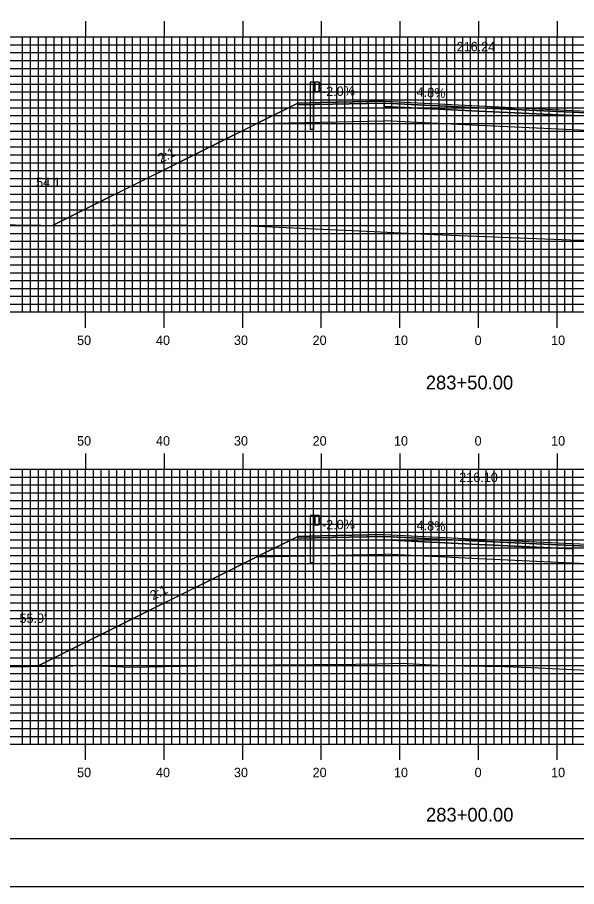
# Model space of a CAD drawing. Extents: x 1811767 to 1812110, y 442591 to 442811.
# Drawn here: x 1811874.3 to 1811945.4, y 442590.5 to 442701.2 of the extents above; entities that cross this region are included whole.
import ezdxf

# ---------------------------------------------------------------- set-up
doc = ezdxf.new("R2010")
doc.units = 0
for name, color, linetype in [('ANNOTATION', 7, 'Continuous'), ('BORDER', 7, 'Continuous'), ('D_Guardrail_Beam_Lt', 7, 'Continuous'), ('D_Roadway_Centerline', 7, 'Continuous'), ('D_Roadway_Centerline_Text', 7, 'Continuous'), ('D_Roadway_Edge_Shoulder', 7, 'Continuous'), ('D_Roadway_Edge_TW', 7, 'Continuous'), ('D_Roadway_Pavement', 7, 'Continuous'), ('D_Roadway_SlopeLines', 7, 'Continuous'), ('D_Roadway_SubGrade', 7, 'Continuous'), ('D_Text_Standard', 7, 'Continuous'), ('H_V ANNOTATION', 7, 'Continuous'), ('MAJOR', 7, 'Continuous'), ('MINOR', 7, 'Continuous'), ('PLOT BOUNDARY', 7, 'Continuous'), ('S_Roadway_Centerline', 7, 'Continuous')]:
    doc.layers.add(name, color=color, linetype=linetype)

msp = doc.modelspace()

# ---------------------------------------------------------------- linework, layer by layer
at = {"layer": 'BORDER'}
msp.add_lwpolyline([(1811783.32, 442596.67), (1812103.32, 442596.67), (1812103.32, 442806.67), (1811783.32, 442806.67)], close=True, dxfattribs=at)
at = {"layer": 'D_Guardrail_Beam_Lt'}
for p, q in [((1811911.49, 442692.91), (1811911.49, 442686.91)), ((1811911.96, 442692.91), (1811911.49, 442692.91)), ((1811912.65, 442692.91), (1811911.96, 442692.91)), ((1811911.96, 442692.91), (1811911.96, 442691.74)), ((1811912.02, 442692.91), (1811912.02, 442691.74)), ((1811912.12, 442692.91), (1811912.12, 442691.74)), ((1811912.65, 442691.74), (1811912.65, 442692.91)), ((1811912.65, 442692.82), (1811912.72, 442692.81)), ((1811912.74, 442692.8), (1811912.88, 442692.7)), ((1811911.96, 442691.74), (1811912.65, 442691.74)), ((1811911.98, 442686.91), (1811911.98, 442691.74)), ((1811912.65, 442692.36), (1811912.65, 442692.29)), ((1811912.72, 442691.84), (1811912.65, 442691.82)), ((1811912.88, 442692.56), (1811912.68, 442692.42)), ((1811912.68, 442692.22), (1811912.88, 442692.09)), ((1811912.88, 442691.94), (1811912.74, 442691.84)), ((1811911.98, 442686.91), (1811911.49, 442686.91)), ((1811911.49, 442637.77), (1811911.49, 442631.77)), ((1811911.96, 442637.77), (1811911.49, 442637.77)), ((1811912.65, 442637.77), (1811911.96, 442637.77)), ((1811911.96, 442637.77), (1811911.96, 442636.6)), ((1811912.02, 442637.77), (1811912.02, 442636.6)), ((1811912.12, 442637.77), (1811912.12, 442636.6)), ((1811912.65, 442636.6), (1811912.65, 442637.77)), ((1811912.65, 442637.68), (1811912.72, 442637.67)), ((1811912.88, 442637.42), (1811912.68, 442637.28)), ((1811912.74, 442637.66), (1811912.88, 442637.56)), ((1811911.96, 442636.6), (1811912.65, 442636.6)), ((1811911.98, 442631.77), (1811911.98, 442636.6)), ((1811912.65, 442637.22), (1811912.65, 442637.15)), ((1811912.72, 442636.7), (1811912.65, 442636.68)), ((1811912.68, 442637.08), (1811912.88, 442636.95)), ((1811912.88, 442636.8), (1811912.74, 442636.7)), ((1811911.98, 442631.77), (1811911.49, 442631.77))]:
    msp.add_line(p, q, dxfattribs=at)
for centre, major_axis, start_param, end_param in [((1811912.71, 442692.77), (0.0417, 0), 0.959931, 1.376053), ((1811912.83, 442692.63), (0.0877, 0), 5.323254, 7.243116), ((1811912.73, 442692.36), (-0.0789, 0), 5.323254, 6.283185), ((1811912.73, 442692.29), (-0.0789, 0), 6.283185, 7.243116), ((1811912.71, 442691.88), (0.0417, 0), 4.907132, 5.323254), ((1811912.83, 442692.01), (0.0877, 0), 5.323254, 7.243116), ((1811912.71, 442637.63), (0.0417, 0), 0.959931, 1.376053), ((1811912.83, 442637.49), (0.0877, 0), 5.323254, 7.243116), ((1811912.73, 442637.22), (-0.0789, 0), 5.323254, 6.283185), ((1811912.73, 442637.15), (-0.0789, 0), 6.283185, 7.243116), ((1811912.71, 442636.74), (0.0417, 0), 4.907132, 5.323254), ((1811912.83, 442636.88), (0.0877, 0), 5.323254, 7.243116)]:
    msp.add_ellipse(centre, major_axis=major_axis, ratio=0.995501, start_param=start_param, end_param=end_param, dxfattribs=at)
at = {"layer": 'D_Roadway_Centerline'}
for points in [[(1811878.79, 442674.7), (1811904.71, 442687.66), (1811909.92, 442690.26), (1811912.92, 442690.32), (1811920.92, 442690.48), (1811932.92, 442689.91), (1811944.92, 442689.33), (1811952.92, 442688.95), (1811955.92, 442688.8), (1811961.45, 442686.04), (1811989.08, 442672.22)], [(1811876.82, 442618.58), (1811904.71, 442632.52), (1811909.92, 442635.12), (1811912.92, 442635.18), (1811920.92, 442635.34), (1811932.92, 442634.77), (1811944.92, 442634.19), (1811952.92, 442633.81), (1811955.92, 442633.66), (1811961.45, 442630.9), (1811989.37, 442616.93)]]:
    msp.add_lwpolyline(points, dxfattribs=at)
at = {"layer": 'D_Roadway_Edge_Shoulder'}
for points in [[(1811920.92, 442690.48), (1811912.92, 442690.32), (1811912.92, 442690.32), (1811909.92, 442690.26), (1811909.92, 442690.01), (1811920.92, 442690.23)], [(1811944.92, 442689.33), (1811952.92, 442688.95), (1811952.92, 442688.95), (1811955.92, 442688.8), (1811955.92, 442688.55), (1811944.92, 442689.08)], [(1811920.92, 442635.34), (1811912.92, 442635.18), (1811912.92, 442635.18), (1811909.92, 442635.12), (1811909.92, 442634.87), (1811920.92, 442635.09)], [(1811944.92, 442634.19), (1811952.92, 442633.81), (1811952.92, 442633.81), (1811955.92, 442633.66), (1811955.92, 442633.41), (1811944.92, 442633.94)]]:
    msp.add_lwpolyline(points, close=True, dxfattribs=at)
at = {"layer": 'D_Roadway_Edge_TW'}
for points in [[(1811920.92, 442690.23), (1811920.92, 442690.48), (1811932.92, 442689.91), (1811944.92, 442689.33), (1811944.92, 442689.08), (1811932.92, 442689.66)], [(1811920.92, 442635.09), (1811920.92, 442635.34), (1811932.92, 442634.77), (1811944.92, 442634.19), (1811944.92, 442633.94), (1811932.92, 442634.52)]]:
    msp.add_lwpolyline(points, close=True, dxfattribs=at)
at = {"layer": 'D_Roadway_Pavement'}
for points in [[(1811920.92, 442689.81), (1811920.92, 442690.23), (1811932.92, 442689.66), (1811944.92, 442689.08), (1811944.92, 442688.66), (1811932.92, 442689.24)], [(1811920.92, 442634.68), (1811920.92, 442635.09), (1811932.92, 442634.52), (1811944.92, 442633.94), (1811944.92, 442633.52), (1811932.92, 442634.1)]]:
    msp.add_lwpolyline(points, close=True, dxfattribs=at)
for points in [[(1811920.92, 442690.23), (1811920.92, 442689.81)], [(1811944.92, 442689.08), (1811944.92, 442688.66)], [(1811920.92, 442635.09), (1811920.92, 442634.68)], [(1811944.92, 442633.94), (1811944.92, 442633.52)]]:
    msp.add_lwpolyline(points, dxfattribs=at)
at = {"layer": 'D_Roadway_SlopeLines'}
for points in [[(1811909.92, 442690.26), (1811878.79, 442674.7)], [(1811909.92, 442635.12), (1811876.82, 442618.58)]]:
    msp.add_lwpolyline(points, dxfattribs=at)
at = {"layer": 'D_Roadway_SubGrade'}
for points in [[(1811920.92, 442689.81), (1811920.92, 442690.23), (1811909.92, 442690.01), (1811909.92, 442690.26), (1811904.71, 442687.66), (1811920.92, 442687.98)], [(1811920.92, 442687.98), (1811920.92, 442690.23), (1811920.92, 442689.81), (1811932.92, 442689.24), (1811944.92, 442688.66), (1811944.92, 442689.08), (1811944.92, 442686.83), (1811932.92, 442687.41)], [(1811944.92, 442688.66), (1811944.92, 442689.08), (1811955.92, 442688.55), (1811955.92, 442688.8), (1811961.45, 442686.04), (1811944.92, 442686.83)], [(1811920.92, 442634.68), (1811920.92, 442635.09), (1811909.92, 442634.87), (1811909.92, 442635.12), (1811904.71, 442632.52), (1811920.92, 442632.84)], [(1811920.92, 442632.84), (1811920.92, 442635.09), (1811920.92, 442634.68), (1811932.92, 442634.1), (1811944.92, 442633.52), (1811944.92, 442633.94), (1811944.92, 442631.69), (1811932.92, 442632.27)], [(1811944.92, 442633.52), (1811944.92, 442633.94), (1811955.92, 442633.41), (1811955.92, 442633.66), (1811961.45, 442630.9), (1811944.92, 442631.69)]]:
    msp.add_lwpolyline(points, close=True, dxfattribs=at)
at = {"layer": 'MAJOR'}
for p, q in [((1811882.92, 442700.67), (1811882.92, 442698.67)), ((1811892.92, 442700.67), (1811892.92, 442698.67)), ((1811902.92, 442700.67), (1811902.92, 442698.67)), ((1811912.92, 442700.67), (1811912.92, 442698.67)), ((1811922.92, 442700.67), (1811922.92, 442698.67)), ((1811932.92, 442700.67), (1811932.92, 442698.67)), ((1811942.92, 442700.67), (1811942.92, 442698.67)), ((1811792.92, 442698.67), (1812072.92, 442698.67)), ((1811792.92, 442698.67), (1812072.92, 442698.67)), ((1811882.92, 442663.67), (1811882.92, 442698.67)), ((1811892.92, 442663.67), (1811892.92, 442698.67)), ((1811902.92, 442663.67), (1811902.92, 442698.67)), ((1811912.92, 442663.67), (1811912.92, 442698.67)), ((1811922.92, 442663.67), (1811922.92, 442698.67)), ((1811932.92, 442663.67), (1811932.92, 442698.67)), ((1811942.92, 442663.67), (1811942.92, 442698.67)), ((1811792.92, 442693.67), (1812072.92, 442693.67)), ((1811792.92, 442688.67), (1812072.92, 442688.67)), ((1811792.92, 442683.67), (1812072.92, 442683.67)), ((1811792.92, 442678.67), (1812072.92, 442678.67)), ((1811792.92, 442673.67), (1812072.92, 442673.67)), ((1811792.92, 442668.67), (1812072.92, 442668.67)), ((1811792.92, 442663.67), (1812072.92, 442663.67)), ((1811792.92, 442663.67), (1812072.92, 442663.67)), ((1811882.92, 442661.66), (1811882.92, 442663.67)), ((1811892.92, 442661.66), (1811892.92, 442663.67)), ((1811902.92, 442661.66), (1811902.92, 442663.67)), ((1811912.92, 442661.66), (1811912.92, 442663.67)), ((1811922.92, 442661.66), (1811922.92, 442663.67)), ((1811932.92, 442661.66), (1811932.92, 442663.67)), ((1811942.92, 442661.66), (1811942.92, 442663.67)), ((1811882.92, 442645.67), (1811882.92, 442643.67)), ((1811892.92, 442645.67), (1811892.92, 442643.67)), ((1811902.92, 442645.67), (1811902.92, 442643.67)), ((1811912.92, 442645.67), (1811912.92, 442643.67)), ((1811922.92, 442645.67), (1811922.92, 442643.67)), ((1811932.92, 442645.67), (1811932.92, 442643.67)), ((1811942.92, 442645.67), (1811942.92, 442643.67)), ((1811792.92, 442643.67), (1812072.92, 442643.67)), ((1811792.92, 442643.67), (1812072.92, 442643.67)), ((1811882.92, 442608.67), (1811882.92, 442643.67)), ((1811892.92, 442608.67), (1811892.92, 442643.67)), ((1811902.92, 442608.67), (1811902.92, 442643.67)), ((1811912.92, 442608.67), (1811912.92, 442643.67)), ((1811922.92, 442608.67), (1811922.92, 442643.67)), ((1811932.92, 442608.67), (1811932.92, 442643.67)), ((1811942.92, 442608.67), (1811942.92, 442643.67)), ((1811792.92, 442638.67), (1812072.92, 442638.67)), ((1811792.92, 442633.67), (1812072.92, 442633.67)), ((1811792.92, 442628.67), (1812072.92, 442628.67)), ((1811792.92, 442623.67), (1812072.92, 442623.67)), ((1811792.92, 442618.67), (1812072.92, 442618.67)), ((1811792.92, 442613.67), (1812072.92, 442613.67)), ((1811792.92, 442608.67), (1812072.92, 442608.67)), ((1811792.92, 442608.67), (1812072.92, 442608.67)), ((1811882.92, 442606.66), (1811882.92, 442608.67)), ((1811892.92, 442606.66), (1811892.92, 442608.67)), ((1811902.92, 442606.66), (1811902.92, 442608.67)), ((1811912.92, 442606.66), (1811912.92, 442608.67)), ((1811922.92, 442606.66), (1811922.92, 442608.67)), ((1811932.92, 442606.66), (1811932.92, 442608.67)), ((1811942.92, 442606.66), (1811942.92, 442608.67))]:
    msp.add_line(p, q, dxfattribs=at)
at = {"layer": 'MINOR'}
for p, q in [((1811874.92, 442663.67), (1811874.92, 442698.67)), ((1811875.92, 442663.67), (1811875.92, 442698.67)), ((1811876.92, 442663.67), (1811876.92, 442698.67)), ((1811877.92, 442663.67), (1811877.92, 442698.67)), ((1811878.92, 442663.67), (1811878.92, 442698.67)), ((1811879.92, 442663.67), (1811879.92, 442698.67)), ((1811880.92, 442663.67), (1811880.92, 442698.67)), ((1811881.92, 442663.67), (1811881.92, 442698.67)), ((1811883.92, 442663.67), (1811883.92, 442698.67)), ((1811884.92, 442663.67), (1811884.92, 442698.67)), ((1811885.92, 442663.67), (1811885.92, 442698.67)), ((1811886.92, 442663.67), (1811886.92, 442698.67)), ((1811887.92, 442663.67), (1811887.92, 442698.67)), ((1811888.92, 442663.67), (1811888.92, 442698.67)), ((1811889.92, 442663.67), (1811889.92, 442698.67)), ((1811890.92, 442663.67), (1811890.92, 442698.67)), ((1811891.92, 442663.67), (1811891.92, 442698.67)), ((1811893.92, 442663.67), (1811893.92, 442698.67)), ((1811894.92, 442663.67), (1811894.92, 442698.67)), ((1811895.92, 442663.67), (1811895.92, 442698.67)), ((1811896.92, 442663.67), (1811896.92, 442698.67)), ((1811897.92, 442663.67), (1811897.92, 442698.67)), ((1811898.92, 442663.67), (1811898.92, 442698.67)), ((1811899.92, 442663.67), (1811899.92, 442698.67)), ((1811900.92, 442663.67), (1811900.92, 442698.67)), ((1811901.92, 442663.67), (1811901.92, 442698.67)), ((1811903.92, 442663.67), (1811903.92, 442698.67)), ((1811904.92, 442663.67), (1811904.92, 442698.67)), ((1811905.92, 442663.67), (1811905.92, 442698.67)), ((1811906.92, 442663.67), (1811906.92, 442698.67)), ((1811907.92, 442663.67), (1811907.92, 442698.67)), ((1811908.92, 442663.67), (1811908.92, 442698.67)), ((1811909.92, 442663.67), (1811909.92, 442698.67)), ((1811910.92, 442663.67), (1811910.92, 442698.67)), ((1811911.92, 442663.67), (1811911.92, 442698.67)), ((1811913.92, 442663.67), (1811913.92, 442698.67)), ((1811914.92, 442663.67), (1811914.92, 442698.67)), ((1811915.92, 442663.67), (1811915.92, 442698.67)), ((1811916.92, 442663.67), (1811916.92, 442698.67)), ((1811917.92, 442663.67), (1811917.92, 442698.67)), ((1811918.92, 442663.67), (1811918.92, 442698.67)), ((1811919.92, 442663.67), (1811919.92, 442698.67)), ((1811920.92, 442663.67), (1811920.92, 442698.67)), ((1811921.92, 442663.67), (1811921.92, 442698.67)), ((1811923.92, 442663.67), (1811923.92, 442698.67)), ((1811924.92, 442663.67), (1811924.92, 442698.67)), ((1811925.92, 442663.67), (1811925.92, 442698.67)), ((1811926.92, 442663.67), (1811926.92, 442698.67)), ((1811927.92, 442663.67), (1811927.92, 442698.67)), ((1811928.92, 442663.67), (1811928.92, 442698.67)), ((1811929.92, 442663.67), (1811929.92, 442698.67)), ((1811930.92, 442663.67), (1811930.92, 442698.67)), ((1811931.92, 442663.67), (1811931.92, 442698.67)), ((1811933.92, 442663.67), (1811933.92, 442698.67)), ((1811934.92, 442663.67), (1811934.92, 442698.67)), ((1811935.92, 442663.67), (1811935.92, 442698.67)), ((1811936.92, 442663.67), (1811936.92, 442698.67)), ((1811937.92, 442663.67), (1811937.92, 442698.67)), ((1811938.92, 442663.67), (1811938.92, 442698.67)), ((1811939.92, 442663.67), (1811939.92, 442698.67)), ((1811940.92, 442663.67), (1811940.92, 442698.67)), ((1811941.92, 442663.67), (1811941.92, 442698.67)), ((1811943.92, 442663.67), (1811943.92, 442698.67)), ((1811944.92, 442663.67), (1811944.92, 442698.67)), ((1811792.92, 442697.67), (1812072.92, 442697.67)), ((1811792.92, 442696.67), (1812072.92, 442696.67)), ((1811792.92, 442695.67), (1812072.92, 442695.67)), ((1811792.92, 442694.67), (1812072.92, 442694.67)), ((1811792.92, 442692.67), (1812072.92, 442692.67)), ((1811792.92, 442691.67), (1812072.92, 442691.67)), ((1811792.92, 442690.67), (1812072.92, 442690.67)), ((1811792.92, 442689.67), (1812072.92, 442689.67)), ((1811792.92, 442687.67), (1812072.92, 442687.67)), ((1811792.92, 442686.67), (1812072.92, 442686.67)), ((1811792.92, 442685.67), (1812072.92, 442685.67)), ((1811792.92, 442684.67), (1812072.92, 442684.67)), ((1811792.92, 442682.67), (1812072.92, 442682.67)), ((1811792.92, 442681.67), (1812072.92, 442681.67)), ((1811792.92, 442680.67), (1812072.92, 442680.67)), ((1811792.92, 442679.67), (1812072.92, 442679.67)), ((1811792.92, 442677.67), (1812072.92, 442677.67)), ((1811792.92, 442676.67), (1812072.92, 442676.67)), ((1811792.92, 442675.67), (1812072.92, 442675.67)), ((1811792.92, 442674.67), (1812072.92, 442674.67)), ((1811792.92, 442672.67), (1812072.92, 442672.67)), ((1811792.92, 442671.67), (1812072.92, 442671.67)), ((1811792.92, 442670.67), (1812072.92, 442670.67)), ((1811792.92, 442669.67), (1812072.92, 442669.67)), ((1811792.92, 442667.67), (1812072.92, 442667.67)), ((1811792.92, 442666.67), (1812072.92, 442666.67)), ((1811792.92, 442665.67), (1812072.92, 442665.67)), ((1811792.92, 442664.67), (1812072.92, 442664.67)), ((1811874.92, 442608.67), (1811874.92, 442643.67)), ((1811875.92, 442608.67), (1811875.92, 442643.67)), ((1811876.92, 442608.67), (1811876.92, 442643.67)), ((1811877.92, 442608.67), (1811877.92, 442643.67)), ((1811878.92, 442608.67), (1811878.92, 442643.67)), ((1811879.92, 442608.67), (1811879.92, 442643.67)), ((1811880.92, 442608.67), (1811880.92, 442643.67)), ((1811881.92, 442608.67), (1811881.92, 442643.67)), ((1811883.92, 442608.67), (1811883.92, 442643.67)), ((1811884.92, 442608.67), (1811884.92, 442643.67)), ((1811885.92, 442608.67), (1811885.92, 442643.67)), ((1811886.92, 442608.67), (1811886.92, 442643.67)), ((1811887.92, 442608.67), (1811887.92, 442643.67)), ((1811888.92, 442608.67), (1811888.92, 442643.67)), ((1811889.92, 442608.67), (1811889.92, 442643.67)), ((1811890.92, 442608.67), (1811890.92, 442643.67)), ((1811891.92, 442608.67), (1811891.92, 442643.67)), ((1811893.92, 442608.67), (1811893.92, 442643.67)), ((1811894.92, 442608.67), (1811894.92, 442643.67)), ((1811895.92, 442608.67), (1811895.92, 442643.67)), ((1811896.92, 442608.67), (1811896.92, 442643.67)), ((1811897.92, 442608.67), (1811897.92, 442643.67)), ((1811898.92, 442608.67), (1811898.92, 442643.67)), ((1811899.92, 442608.67), (1811899.92, 442643.67)), ((1811900.92, 442608.67), (1811900.92, 442643.67)), ((1811901.92, 442608.67), (1811901.92, 442643.67)), ((1811903.92, 442608.67), (1811903.92, 442643.67)), ((1811904.92, 442608.67), (1811904.92, 442643.67)), ((1811905.92, 442608.67), (1811905.92, 442643.67)), ((1811906.92, 442608.67), (1811906.92, 442643.67)), ((1811907.92, 442608.67), (1811907.92, 442643.67)), ((1811908.92, 442608.67), (1811908.92, 442643.67)), ((1811909.92, 442608.67), (1811909.92, 442643.67)), ((1811910.92, 442608.67), (1811910.92, 442643.67)), ((1811911.92, 442608.67), (1811911.92, 442643.67)), ((1811913.92, 442608.67), (1811913.92, 442643.67)), ((1811914.92, 442608.67), (1811914.92, 442643.67)), ((1811915.92, 442608.67), (1811915.92, 442643.67)), ((1811916.92, 442608.67), (1811916.92, 442643.67)), ((1811917.92, 442608.67), (1811917.92, 442643.67)), ((1811918.92, 442608.67), (1811918.92, 442643.67)), ((1811919.92, 442608.67), (1811919.92, 442643.67)), ((1811920.92, 442608.67), (1811920.92, 442643.67)), ((1811921.92, 442608.67), (1811921.92, 442643.67)), ((1811923.92, 442608.67), (1811923.92, 442643.67)), ((1811924.92, 442608.67), (1811924.92, 442643.67)), ((1811925.92, 442608.67), (1811925.92, 442643.67)), ((1811926.92, 442608.67), (1811926.92, 442643.67)), ((1811927.92, 442608.67), (1811927.92, 442643.67)), ((1811928.92, 442608.67), (1811928.92, 442643.67)), ((1811929.92, 442608.67), (1811929.92, 442643.67)), ((1811930.92, 442608.67), (1811930.92, 442643.67)), ((1811931.92, 442608.67), (1811931.92, 442643.67)), ((1811933.92, 442608.67), (1811933.92, 442643.67)), ((1811934.92, 442608.67), (1811934.92, 442643.67)), ((1811935.92, 442608.67), (1811935.92, 442643.67)), ((1811936.92, 442608.67), (1811936.92, 442643.67)), ((1811937.92, 442608.67), (1811937.92, 442643.67)), ((1811938.92, 442608.67), (1811938.92, 442643.67)), ((1811939.92, 442608.67), (1811939.92, 442643.67)), ((1811940.92, 442608.67), (1811940.92, 442643.67)), ((1811941.92, 442608.67), (1811941.92, 442643.67)), ((1811943.92, 442608.67), (1811943.92, 442643.67)), ((1811944.92, 442608.67), (1811944.92, 442643.67)), ((1811792.92, 442642.67), (1812072.92, 442642.67)), ((1811792.92, 442641.67), (1812072.92, 442641.67)), ((1811792.92, 442640.67), (1812072.92, 442640.67)), ((1811792.92, 442639.67), (1812072.92, 442639.67)), ((1811792.92, 442637.67), (1812072.92, 442637.67)), ((1811792.92, 442636.67), (1812072.92, 442636.67)), ((1811792.92, 442635.67), (1812072.92, 442635.67)), ((1811792.92, 442634.67), (1812072.92, 442634.67)), ((1811792.92, 442632.67), (1812072.92, 442632.67)), ((1811792.92, 442631.67), (1812072.92, 442631.67)), ((1811792.92, 442630.67), (1812072.92, 442630.67)), ((1811792.92, 442629.67), (1812072.92, 442629.67)), ((1811792.92, 442627.67), (1812072.92, 442627.67)), ((1811792.92, 442626.67), (1812072.92, 442626.67)), ((1811792.92, 442625.67), (1812072.92, 442625.67)), ((1811792.92, 442624.67), (1812072.92, 442624.67)), ((1811792.92, 442622.67), (1812072.92, 442622.67)), ((1811792.92, 442621.67), (1812072.92, 442621.67)), ((1811792.92, 442620.67), (1812072.92, 442620.67)), ((1811792.92, 442619.67), (1812072.92, 442619.67)), ((1811792.92, 442617.67), (1812072.92, 442617.67)), ((1811792.92, 442616.67), (1812072.92, 442616.67)), ((1811792.92, 442615.67), (1812072.92, 442615.67)), ((1811792.92, 442614.67), (1812072.92, 442614.67)), ((1811792.92, 442612.67), (1812072.92, 442612.67)), ((1811792.92, 442611.67), (1812072.92, 442611.67)), ((1811792.92, 442610.67), (1812072.92, 442610.67)), ((1811792.92, 442609.67), (1812072.92, 442609.67))]:
    msp.add_line(p, q, dxfattribs=at)
at = {"layer": 'PLOT BOUNDARY'}
msp.add_lwpolyline([(1811767.13, 442590.55), (1812107.13, 442590.55), (1812107.13, 442810.55), (1811767.13, 442810.55)], close=True, dxfattribs=at)
at = {"layer": 'S_Roadway_Centerline'}
for points in [[(1811792.92, 442675.29), (1811793.32, 442675.31), (1811798.45, 442675.57), (1811809.64, 442675.71), (1811818.69, 442675.7), (1811828.62, 442675.81), (1811833.93, 442675.93), (1811840.94, 442675.65), (1811851.46, 442674.96), (1811854.3, 442674.89), (1811861.95, 442674.83), (1811870.61, 442674.79), (1811880.53, 442674.68), (1811891.99, 442674.77), (1811903.84, 442674.62), (1811919.63, 442673.92), (1811927.29, 442673.55), (1811944.65, 442672.84), (1811951.76, 442672.74), (1811969.82, 442672.4), (1811979.59, 442672.39), (1811993.71, 442672.13)], [(1811870, 442618.46), (1811884.1, 442618.7), (1811888.51, 442618.47), (1811901.52, 442618.74), (1811917.28, 442618.87), (1811920.11, 442618.9), (1811923.12, 442618.97), (1811928.49, 442618.7), (1811936.28, 442618.54), (1811939.65, 442618.42), (1811951.32, 442617.88), (1811958.09, 442617.63), (1811960.18, 442617.58), (1811965.22, 442617.36), (1811976.05, 442617), (1811984.1, 442616.8), (1811994.98, 442617.07)]]:
    msp.add_lwpolyline(points, dxfattribs=at)

# ---------------------------------------------------------------- texts
at = {"layer": 'ANNOTATION'}
for s, rotation, p in [('-2.0%', 1.1458, (1811913.02, 442691.12)), ('4.8%', 357.2519, (1811925.04, 442691.09)), ('2:1', 26.5651, (1811892.5, 442682.59)), ('-2.0%', 1.1458, (1811913.02, 442635.98)), ('4.8%', 357.2519, (1811925.04, 442635.95)), ('2:1', 26.5651, (1811891.51, 442626.96))]:
    msp.add_text(s, height=1.2, rotation=rotation, dxfattribs=at).set_placement(p)
at = {"layer": 'D_Roadway_Centerline'}
for s, p in [('C', (1811932.91, 442689.91)), ('L', (1811932.92, 442689.9)), ('C', (1811932.91, 442634.77)), ('L', (1811932.92, 442634.76))]:
    msp.add_text(s, height=0.0146, dxfattribs=at).set_placement(p)
at = {"layer": 'D_Roadway_Centerline_Text'}
for s, p in [('216.24', (1811930.15, 442696.84)), ('216.10', (1811930.48, 442642.03))]:
    msp.add_text(s, height=1.2, dxfattribs=at).set_placement(p)
at = {"layer": 'D_Text_Standard'}
for s, p in [("54.1'", (1811876.63, 442679.58)), ("55.9'", (1811874.52, 442624.1))]:
    msp.add_text(s, height=1.2, dxfattribs=at).set_placement(p)
at = {"layer": 'H_V ANNOTATION'}
for s, height, p in [('50', 1.2, (1811881.85, 442659.47)), ('40', 1.2, (1811891.89, 442659.47)), ('30', 1.2, (1811901.81, 442659.47)), ('20', 1.2, (1811911.82, 442659.47)), ('10', 1.2, (1811922.17, 442659.47)), ('0', 1.2, (1811932.43, 442659.47)), ('10', 1.2, (1811942.17, 442659.47)), ('283+50.00', 1.75, (1811926.22, 442653.82)), ('50', 1.2, (1811881.85, 442646.67)), ('40', 1.2, (1811891.89, 442646.67)), ('30', 1.2, (1811901.81, 442646.67)), ('20', 1.2, (1811911.82, 442646.67)), ('10', 1.2, (1811922.17, 442646.67)), ('0', 1.2, (1811932.43, 442646.67)), ('10', 1.2, (1811942.17, 442646.67)), ('50', 1.2, (1811881.85, 442604.47)), ('40', 1.2, (1811891.89, 442604.47)), ('30', 1.2, (1811901.81, 442604.47)), ('20', 1.2, (1811911.82, 442604.47)), ('10', 1.2, (1811922.17, 442604.47)), ('0', 1.2, (1811932.43, 442604.47)), ('10', 1.2, (1811942.17, 442604.47)), ('283+00.00', 1.75, (1811926.25, 442598.82))]:
    msp.add_text(s, height=height, dxfattribs=at).set_placement(p)

doc.saveas('drawing.dxf')
